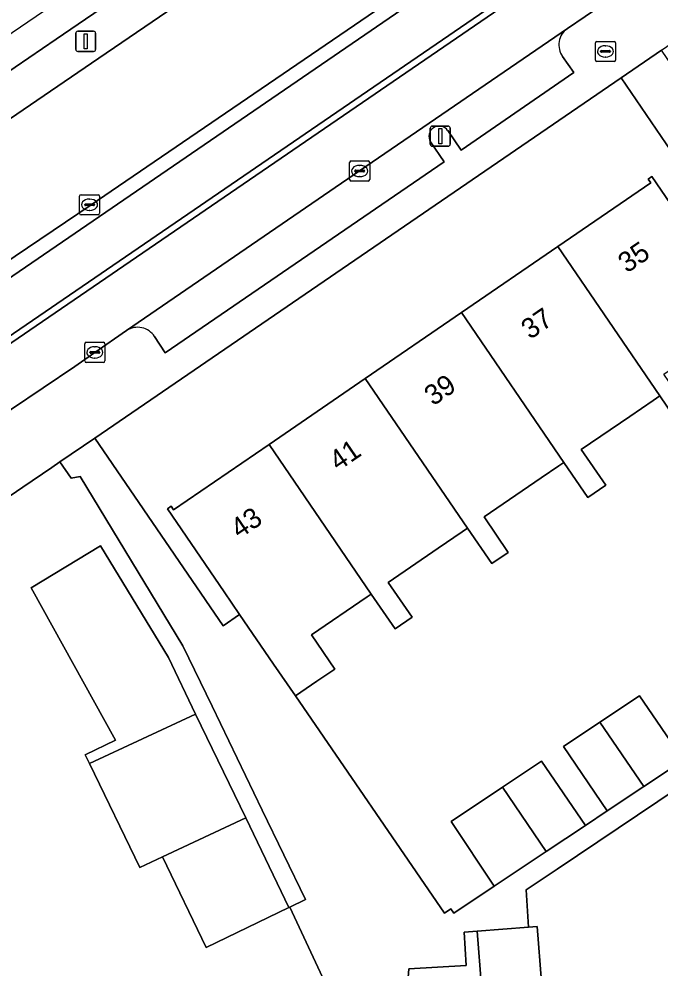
# Model space of a CAD drawing. Extents: x 158086 to 159499, y 382904 to 383981.
# Drawn here: x 158546.2 to 158578.09, y 383559.01 to 383606.24 of the extents above; entities that cross this region are included whole.
import ezdxf

# ---------------------------------------------------------------- set-up
doc = ezdxf.new("R2010")
doc.units = 0
for name, color, linetype in [('IMGEO_Berm_groen', 7, 'Continuous'), ('IMGEO_Brandkraan', 7, 'Continuous'), ('IMGEO_Erf', 7, 'Continuous'), ('IMGEO_Fietspad_gesloten', 7, 'Continuous'), ('IMGEO_Groenvoorziening', 7, 'Continuous'), ('IMGEO_Haag', 7, 'Continuous'), ('IMGEO_Kolk', 7, 'Continuous'), ('IMGEO_Lichtmast', 7, 'Continuous'), ('IMGEO_OVBaan_gesloten', 7, 'Continuous'), ('IMGEO_Pand', 7, 'Continuous'), ('IMGEO_Pand_nummerreeks', 7, 'Continuous'), ('IMGEO_Parkeervlak_open', 7, 'Continuous'), ('IMGEO_Rijbaan_lokaal_open', 7, 'Continuous'), ('IMGEO_Rijbaan_regionaal_gesloten', 7, 'Continuous'), ('IMGEO_Verkeerseiland_open', 7, 'Continuous'), ('IMGEO_Voetpad_open', 7, 'Continuous')]:
    doc.layers.add(name, color=color, linetype=linetype)

msp = doc.modelspace()

# ---------------------------------------------------------------- linework, layer by layer
at = {"layer": 'IMGEO_Berm_groen'}
msp.add_lwpolyline([(158661.52, 383682.534), (158548.056, 383605.231), (158537.837, 383598.268), (158500, 383572.487), (158425.464, 383521.701), (158412.679, 383512.917), (158399.643, 383503.685), (158401.599, 383501.25), (158412.794, 383510.243), (158418.409, 383514.401), (158426.656, 383520.079), (158500, 383570.082), (158538.968, 383596.649), (158549.805, 383604.037), (158646.334, 383669.776)], dxfattribs=at)
at = {"layer": 'IMGEO_Brandkraan'}
for p, q in [((158574.875, 383604.198), (158574.875, 383605.05)), ((158574.95, 383605.124), (158575.802, 383605.124)), ((158575.363, 383604.904), (158575.388, 383604.904)), ((158575.876, 383605.05), (158575.876, 383604.198)), ((158575.134, 383604.618), (158575.134, 383604.63)), ((158575.572, 383604.581), (158575.174, 383604.581)), ((158575.177, 383604.667), (158575.575, 383604.667)), ((158575.386, 383604.344), (158575.361, 383604.344)), ((158575.618, 383604.63), (158575.618, 383604.618)), ((158575.802, 383604.124), (158574.95, 383604.124))]:
    msp.add_line(p, q, dxfattribs=at)
for points in [[(158574.875, 383604.198), (158574.875, 383605.05)], [(158574.95, 383605.124), (158575.802, 383605.124)], [(158575.876, 383605.05), (158575.876, 383604.198)], [(158575.802, 383604.124), (158574.95, 383604.124)]]:
    msp.add_lwpolyline(points, dxfattribs=at)
for centre, radius, start, end in [((158574.952, 383605.048), 0.0765, 91.552, 178.448), ((158574.952, 383605.048), 0.0765, 91.552, 178.448), ((158575.8, 383605.048), 0.0765, 1.552, 88.448), ((158575.8, 383605.048), 0.0765, 1.552, 88.448), ((158575.174, 383604.627), 0.0403, 85.8775, 175.7526), ((158575.171, 383604.617), 0.0366, 178.938, 274.7102), ((158575.575, 383604.624), 0.043, 264.8664, 352.4533), ((158575.579, 383604.629), 0.0386, 1.7309, 96.639), ((158574.952, 383604.2), 0.0765, 181.552, 268.448), ((158574.952, 383604.2), 0.0765, 181.552, 268.448), ((158575.8, 383604.2), 0.0765, 271.552, 358.448), ((158575.8, 383604.2), 0.0765, 271.552, 358.448)]:
    msp.add_arc(centre, radius, start, end, dxfattribs=at)
for centre, major_axis, ratio, start_param, end_param in [((158575.362, 383604.624), (-0.387, 0.002), 0.722429, 4.712389, 7.853982), ((158575.387, 383604.624), (-0.39, 0.002), 0.717154, 1.570796, 4.712389)]:
    msp.add_ellipse(centre, major_axis=major_axis, ratio=ratio, start_param=start_param, end_param=end_param, dxfattribs=at)
at = {"layer": 'IMGEO_Erf'}
for points in [[(158579.136, 383598.942), (158576.159, 383603.317), (158549.967, 383585.398), (158556.351, 383576.067), (158557.177, 383576.632), (158556.403, 383577.764), (158553.583, 383581.893), (158553.765, 383582.018), (158553.889, 383581.835), (158558.644, 383585.092), (158563.43, 383588.37), (158568.214, 383591.647), (158573, 383594.925), (158577.626, 383598.094), (158577.502, 383598.276), (158577.683, 383598.4), (158582.567, 383591.251)], [(158579.125, 383585.956), (158578.072, 383587.498), (158577.748, 383587.277), (158576.58, 383586.479), (158574.174, 383584.837), (158575.386, 383583.063), (158574.494, 383582.453), (158573.305, 383584.194), (158573.059, 383584.026), (158572.184, 383583.429), (158569.339, 383581.485), (158570.543, 383579.723), (158569.719, 383579.16), (158568.513, 383580.926), (158568.251, 383580.747), (158567.051, 383579.927), (158564.567, 383578.231), (158565.754, 383576.493), (158564.911, 383575.917), (158563.728, 383577.649), (158563.528, 383577.513), (158560.75, 383575.617), (158561.909, 383573.92), (158561.021, 383573.313), (158559.951, 383572.583), (158567.367, 383561.781), (158567.688, 383561.995), (158567.831, 383561.781), (158569.84, 383563.12), (158567.693, 383566.339), (158570.248, 383568.043), (158572.194, 383569.34), (158574.377, 383566.145), (158575.464, 383566.87), (158573.281, 383570.065), (158575.095, 383571.274), (158577.07, 383572.59), (158579.253, 383569.396)], [(158561.415, 383558.361), (158559.676, 383562.084), (158560.448, 383562.457), (158558.299, 383566.908), (158555.807, 383572.069), (158554.353, 383575.08), (158549.253, 383583.496), (158548.789, 383583.404), (158548.236, 383584.214), (158547.843, 383583.945), (158546.401, 383582.959), (158522.545, 383566.673), (158524.505, 383562.65), (158524.784, 383562.729), (158527.266, 383557.496)], [(158596.657, 383500), (158593.057, 383565.667), (158592.687, 383565.654), (158592.05, 383576.787), (158572.97, 383563.972), (158571.433, 383562.939), (158571.548, 383561.088), (158571.981, 383561.122), (158572.196, 383558.372)], [(158569.201, 383558.139), (158568.986, 383560.888), (158568.35, 383560.848), (158568.454, 383559.19), (158565.586, 383559.012), (158565.569, 383558.593)]]:
    msp.add_lwpolyline(points, dxfattribs=at)
msp.add_lwpolyline([(158554.988, 383571.686), (158557.48, 383566.525), (158559.633, 383562.064), (158555.519, 383560.077), (158553.341, 383564.589), (158552.205, 383564.058), (158549.711, 383569.223), (158549.501, 383569.658), (158551.003, 383570.383), (158546.803, 383577.957), (158550.263, 383580.053), (158553.631, 383574.496)], close=True, dxfattribs=at)
at = {"layer": 'IMGEO_Fietspad_gesloten'}
for points in [[(158406.477, 383492.138), (158407.038, 383492.595), (158415.949, 383500), (158420.474, 383503.76), (158424.552, 383506.994), (158427.887, 383509.53), (158436.47, 383515.388), (158443.607, 383520.298), (158444.263, 383520.715), (158445.933, 383521.775), (158446.621, 383522.245), (158446.476, 383522.514), (158500, 383559.162), (158541.26, 383587.412), (158544.075, 383589.339), (158618.844, 383640.502), (158640.443, 383655.157), (158646.899, 383659.567), (158648.236, 383660.378)], [(158643.219, 383659.898), (158616.779, 383641.989), (158544.359, 383592.419), (158542.712, 383591.29), (158500, 383562.025), (158434.999, 383517.487), (158427.133, 383512.095)]]:
    msp.add_lwpolyline(points, dxfattribs=at)
at = {"layer": 'IMGEO_Groenvoorziening'}
for points in [[(158427.133, 383512.095), (158434.999, 383517.487), (158500, 383562.025), (158542.712, 383591.29), (158544.359, 383592.419), (158616.779, 383641.989), (158643.219, 383659.898)], [(158609.643, 383637.826), (158596.373, 383628.777), (158581.924, 383618.931), (158567.48, 383609.075), (158549.745, 383596.961), (158545.402, 383594.03), (158542.284, 383591.903), (158520.007, 383576.707), (158505.553, 383566.876), (158500, 383563.101), (158493.571, 383558.73), (158476.685, 383547.207), (158462.204, 383537.344), (158446.926, 383526.907), (158434.349, 383518.331)]]:
    msp.add_lwpolyline(points, dxfattribs=at)
at = {"layer": 'IMGEO_Haag'}
for points in [[(158427.133, 383512.095), (158434.999, 383517.487), (158500, 383562.025), (158542.712, 383591.29), (158544.359, 383592.419), (158616.779, 383641.989), (158643.219, 383659.898)], [(158609.643, 383637.826), (158596.373, 383628.777), (158581.924, 383618.931), (158567.48, 383609.075), (158549.745, 383596.961), (158545.402, 383594.03), (158542.284, 383591.903), (158520.007, 383576.707), (158505.553, 383566.876), (158500, 383563.101), (158493.571, 383558.73), (158476.685, 383547.207), (158462.204, 383537.344), (158446.926, 383526.907), (158434.349, 383518.331)]]:
    msp.add_lwpolyline(points, dxfattribs=at)
at = {"layer": 'IMGEO_Kolk'}
for p, q in [((158562.649, 383598.254), (158562.649, 383599.106)), ((158562.724, 383599.18), (158563.576, 383599.18)), ((158563.65, 383599.106), (158563.65, 383598.254)), ((158562.908, 383598.674), (158562.908, 383598.686)), ((158563.346, 383598.637), (158562.948, 383598.637)), ((158562.951, 383598.723), (158563.349, 383598.723)), ((158563.137, 383598.96), (158563.162, 383598.96)), ((158563.392, 383598.686), (158563.392, 383598.674)), ((158563.576, 383598.18), (158562.724, 383598.18)), ((158563.16, 383598.4), (158563.135, 383598.4)), ((158549.213, 383596.576), (158549.213, 383597.428)), ((158549.288, 383597.502), (158550.14, 383597.502)), ((158549.701, 383597.282), (158549.726, 383597.282)), ((158550.214, 383597.428), (158550.214, 383596.576)), ((158549.472, 383596.996), (158549.472, 383597.008)), ((158549.91, 383596.959), (158549.512, 383596.959)), ((158549.515, 383597.045), (158549.913, 383597.045)), ((158549.724, 383596.722), (158549.699, 383596.722)), ((158549.956, 383597.008), (158549.956, 383596.996)), ((158550.14, 383596.502), (158549.288, 383596.502)), ((158549.547, 383590.163), (158550.399, 383590.163)), ((158549.472, 383589.237), (158549.472, 383590.089)), ((158549.731, 383589.657), (158549.731, 383589.669)), ((158549.774, 383589.706), (158550.172, 383589.706)), ((158549.96, 383589.943), (158549.985, 383589.943)), ((158550.215, 383589.669), (158550.215, 383589.657)), ((158550.473, 383590.089), (158550.473, 383589.237)), ((158550.169, 383589.62), (158549.771, 383589.62)), ((158549.983, 383589.383), (158549.958, 383589.383)), ((158550.399, 383589.163), (158549.547, 383589.163))]:
    msp.add_line(p, q, dxfattribs=at)
for points in [[(158562.649, 383598.254), (158562.649, 383599.106)], [(158562.724, 383599.18), (158563.576, 383599.18)], [(158563.65, 383599.106), (158563.65, 383598.254)], [(158563.576, 383598.18), (158562.724, 383598.18)], [(158549.213, 383596.576), (158549.213, 383597.428)], [(158549.288, 383597.502), (158550.14, 383597.502)], [(158550.214, 383597.428), (158550.214, 383596.576)], [(158550.14, 383596.502), (158549.288, 383596.502)], [(158549.547, 383590.163), (158550.399, 383590.163)], [(158549.472, 383589.237), (158549.472, 383590.089)], [(158550.473, 383590.089), (158550.473, 383589.237)], [(158550.399, 383589.163), (158549.547, 383589.163)]]:
    msp.add_lwpolyline(points, dxfattribs=at)
for centre, radius, start, end in [((158562.726, 383599.104), 0.0765, 91.552, 178.448), ((158562.726, 383599.104), 0.0765, 91.552, 178.448), ((158563.574, 383599.104), 0.0765, 1.552, 88.448), ((158563.574, 383599.104), 0.0765, 1.552, 88.448), ((158562.948, 383598.683), 0.0403, 85.8775, 175.7526), ((158562.945, 383598.673), 0.0366, 178.938, 274.7102), ((158563.349, 383598.68), 0.043, 264.8664, 352.4533), ((158563.353, 383598.685), 0.0386, 1.7309, 96.639), ((158562.726, 383598.256), 0.0765, 181.552, 268.448), ((158562.726, 383598.256), 0.0765, 181.552, 268.448), ((158563.574, 383598.256), 0.0765, 271.552, 358.448), ((158563.574, 383598.256), 0.0765, 271.552, 358.448), ((158549.29, 383597.426), 0.0765, 91.552, 178.448), ((158549.29, 383597.426), 0.0765, 91.552, 178.448), ((158550.138, 383597.426), 0.0765, 1.552, 88.448), ((158550.138, 383597.426), 0.0765, 1.552, 88.448), ((158549.512, 383597.005), 0.0403, 85.8775, 175.7526), ((158549.509, 383596.995), 0.0366, 178.938, 274.7102), ((158549.913, 383597.002), 0.043, 264.8664, 352.4533), ((158549.917, 383597.007), 0.0386, 1.7309, 96.639), ((158549.29, 383596.578), 0.0765, 181.552, 268.448), ((158549.29, 383596.578), 0.0765, 181.552, 268.448), ((158550.138, 383596.578), 0.0765, 271.552, 358.448), ((158550.138, 383596.578), 0.0765, 271.552, 358.448), ((158549.549, 383590.087), 0.0765, 91.552, 178.448), ((158549.549, 383590.087), 0.0765, 91.552, 178.448), ((158550.397, 383590.087), 0.0765, 1.552, 88.448), ((158550.397, 383590.087), 0.0765, 1.552, 88.448), ((158549.771, 383589.666), 0.0403, 85.8775, 175.7526), ((158549.768, 383589.656), 0.0366, 178.938, 274.7102), ((158550.172, 383589.663), 0.043, 264.8664, 352.4533), ((158550.176, 383589.668), 0.0386, 1.7309, 96.639), ((158549.549, 383589.239), 0.0765, 181.552, 268.448), ((158549.549, 383589.239), 0.0765, 181.552, 268.448), ((158550.397, 383589.239), 0.0765, 271.552, 358.448), ((158550.397, 383589.239), 0.0765, 271.552, 358.448)]:
    msp.add_arc(centre, radius, start, end, dxfattribs=at)
for centre, major_axis, ratio, start_param, end_param in [((158563.136, 383598.68), (-0.387, 0.002), 0.722429, 4.712389, 7.853982), ((158563.161, 383598.68), (-0.39, 0.002), 0.717154, 1.570796, 4.712389), ((158549.7, 383597.002), (-0.387, 0.002), 0.722429, 4.712389, 7.853982), ((158549.725, 383597.002), (-0.39, 0.002), 0.717154, 1.570796, 4.712389), ((158549.959, 383589.663), (-0.387, 0.002), 0.722429, 4.712389, 7.853982), ((158549.984, 383589.663), (-0.39, 0.002), 0.717154, 1.570796, 4.712389)]:
    msp.add_ellipse(centre, major_axis=major_axis, ratio=ratio, start_param=start_param, end_param=end_param, dxfattribs=at)
at = {"layer": 'IMGEO_Lichtmast'}
for p, q in [((158549.025, 383604.725), (158549.025, 383605.525)), ((158549.025, 383605.525), (158549.025, 383604.725)), ((158549.125, 383605.625), (158549.915, 383605.625)), ((158549.915, 383605.625), (158549.125, 383605.625)), ((158550.015, 383605.525), (158550.015, 383604.725)), ((158550.015, 383604.725), (158550.015, 383605.525)), ((158549.915, 383604.625), (158549.125, 383604.625)), ((158549.125, 383604.625), (158549.915, 383604.625)), ((158566.662, 383600.011), (158566.662, 383600.811)), ((158566.662, 383600.811), (158566.662, 383600.011)), ((158566.762, 383600.911), (158567.552, 383600.911)), ((158567.552, 383600.911), (158566.762, 383600.911)), ((158567.652, 383600.811), (158567.652, 383600.011)), ((158567.652, 383600.011), (158567.652, 383600.811)), ((158567.552, 383599.911), (158566.762, 383599.911)), ((158566.762, 383599.911), (158567.552, 383599.911))]:
    msp.add_line(p, q, dxfattribs=at)
for points in [[(158549.445, 383605.5), (158549.595, 383605.5), (158549.595, 383604.75), (158549.445, 383604.75), (158549.445, 383605.5)], [(158567.082, 383600.786), (158567.232, 383600.786), (158567.232, 383600.036), (158567.082, 383600.036), (158567.082, 383600.786)]]:
    msp.add_lwpolyline(points, dxfattribs=at)
for centre, start, end in [((158549.125, 383605.525), 90, 180), ((158549.125, 383605.525), 90, 180), ((158549.915, 383605.525), 0, 90), ((158549.915, 383605.525), 360, 90), ((158549.125, 383604.725), 180, 270), ((158549.125, 383604.725), 180, 270), ((158549.915, 383604.725), 270, 0), ((158549.915, 383604.725), 270, 0), ((158566.762, 383600.811), 90, 180), ((158566.762, 383600.811), 90, 180), ((158567.552, 383600.811), 0, 90), ((158567.552, 383600.811), 360, 90), ((158566.762, 383600.011), 180, 270), ((158566.762, 383600.011), 180, 270), ((158567.552, 383600.011), 270, 0), ((158567.552, 383600.011), 270, 0)]:
    msp.add_arc(centre, 0.1, start, end, dxfattribs=at)
at = {"layer": 'IMGEO_OVBaan_gesloten'}
msp.add_lwpolyline([(158637.817, 383668.138), (158540.809, 383602.111), (158416.544, 383517.531), (158365.354, 383481.561), (158366.291, 383480.217), (158366.7, 383480.506), (158367.706, 383481.204), (158382.012, 383491.237), (158388.342, 383495.7), (158394.487, 383500), (158394.668, 383500.127), (158398.126, 383502.611), (158399.643, 383503.685), (158412.679, 383512.917), (158425.464, 383521.701), (158500, 383572.487), (158537.837, 383598.268), (158548.056, 383605.231), (158661.52, 383682.534)], dxfattribs=at)
at = {"layer": 'IMGEO_Pand'}
for points in [[(158577.683, 383598.4), (158577.502, 383598.276), (158577.626, 383598.094), (158573, 383594.925), (158578.072, 383587.498), (158579.125, 383585.956), (158579.775, 383586.4), (158578.278, 383588.588), (158582.262, 383591.308), (158582.386, 383591.126), (158582.567, 383591.251)], [(158573, 383594.925), (158568.214, 383591.647), (158573.305, 383584.194), (158574.494, 383582.453), (158575.386, 383583.063), (158574.174, 383584.837), (158576.58, 383586.479), (158577.748, 383587.277), (158578.072, 383587.498)], [(158568.214, 383591.647), (158563.43, 383588.37), (158568.513, 383580.926), (158569.719, 383579.16), (158570.543, 383579.723), (158569.339, 383581.485), (158572.184, 383583.429), (158573.059, 383584.026), (158573.305, 383584.194)], [(158563.43, 383588.37), (158558.644, 383585.092), (158563.728, 383577.649), (158564.911, 383575.917), (158565.754, 383576.493), (158564.567, 383578.231), (158567.051, 383579.927), (158568.251, 383580.747), (158568.513, 383580.926)], [(158558.644, 383585.092), (158553.889, 383581.835), (158553.765, 383582.018), (158553.583, 383581.893), (158556.403, 383577.764), (158557.177, 383576.632), (158558.867, 383574.161), (158559.951, 383572.583), (158561.021, 383573.313), (158561.909, 383573.92), (158560.75, 383575.617), (158563.528, 383577.513), (158563.728, 383577.649)], [(158549.711, 383569.223), (158554.988, 383571.686), (158553.631, 383574.496), (158550.263, 383580.053), (158546.803, 383577.957), (158551.003, 383570.383), (158549.501, 383569.658)], [(158577.07, 383572.59), (158575.095, 383571.274), (158577.278, 383568.079), (158579.253, 383569.396)], [(158554.988, 383571.686), (158549.711, 383569.223), (158552.205, 383564.058), (158553.341, 383564.589), (158557.48, 383566.525)], [(158575.095, 383571.274), (158573.281, 383570.065), (158575.464, 383566.87), (158577.278, 383568.079)], [(158572.194, 383569.34), (158570.248, 383568.043), (158572.431, 383564.848), (158574.377, 383566.145)], [(158570.248, 383568.043), (158567.693, 383566.339), (158569.84, 383563.12), (158572.431, 383564.848)], [(158557.48, 383566.525), (158553.341, 383564.589), (158555.519, 383560.077), (158559.633, 383562.064)], [(158571.548, 383561.088), (158568.986, 383560.888), (158569.201, 383558.139), (158572.196, 383558.372), (158571.981, 383561.122)]]:
    msp.add_lwpolyline(points, close=True, dxfattribs=at)
at = {"layer": 'IMGEO_Parkeervlak_open'}
for points in [[(158573.479, 383605.764), (158563.146, 383598.681), (158551.551, 383590.748)], [(158567.526, 383600.691), (158568.201, 383599.715), (158573.8, 383603.57), (158573.246, 383604.372)], [(158552.944, 383590.449), (158553.476, 383589.647), (158567.352, 383599.137), (158566.676, 383600.126)]]:
    msp.add_lwpolyline(points, dxfattribs=at)
for centre, radius, start, end in [((158574.044, 383604.954), 0.988, 124.9067, 216.0885), ((158567.104, 383600.404), 0.51, 34.1912, 213.0332), ((158552.099, 383589.906), 1.005, 32.7348, 123.0364)]:
    msp.add_arc(centre, radius, start, end, dxfattribs=at)
at = {"layer": 'IMGEO_Rijbaan_lokaal_open'}
for points in [[(158646.837, 383659.134), (158640.621, 383654.875), (158619.029, 383640.224), (158544.259, 383589.076), (158541.457, 383587.159), (158500, 383558.782), (158446.621, 383522.245), (158445.933, 383521.775)], [(158509.297, 383561.87), (158518.272, 383568.017), (158520.325, 383569.401), (158527.122, 383574.06), (158535.161, 383579.515), (158543.008, 383584.914), (158543.436, 383585.211), (158545.232, 383586.434), (158545.824, 383586.835), (158548.973, 383588.965), (158549.969, 383589.664), (158551.551, 383590.748), (158563.146, 383598.681), (158573.479, 383605.764), (158577, 383608.163)]]:
    msp.add_lwpolyline(points, dxfattribs=at)
at = {"layer": 'IMGEO_Rijbaan_regionaal_gesloten'}
for points in [[(158646.334, 383669.776), (158549.805, 383604.037), (158538.968, 383596.649), (158500, 383570.082), (158426.656, 383520.079)], [(158434.349, 383518.331), (158446.926, 383526.907), (158462.204, 383537.344), (158476.685, 383547.207), (158493.571, 383558.73), (158500, 383563.101), (158505.553, 383566.876), (158520.007, 383576.707), (158542.284, 383591.903), (158545.402, 383594.03), (158549.745, 383596.961), (158567.48, 383609.075), (158581.924, 383618.931), (158596.373, 383628.777), (158609.643, 383637.826)]]:
    msp.add_lwpolyline(points, dxfattribs=at)
at = {"layer": 'IMGEO_Verkeerseiland_open'}
msp.add_lwpolyline([(158649.379, 383658.827), (158648.905, 383659.524), (158648.236, 383660.378), (158646.899, 383659.567), (158640.443, 383655.157), (158618.844, 383640.502), (158544.075, 383589.339), (158541.26, 383587.412), (158500, 383559.162), (158446.476, 383522.514), (158446.621, 383522.245), (158500, 383558.782), (158541.457, 383587.159), (158544.259, 383589.076), (158619.029, 383640.224), (158640.621, 383654.875), (158646.837, 383659.134)], dxfattribs=at)
at = {"layer": 'IMGEO_Voetpad_open'}
for points in [[(158583.69, 383608.497), (158588.804, 383611.969), (158588.809, 383611.645), (158588.859, 383611.241), (158592.055, 383614.205), (158595.723, 383620.99), (158590.586, 383617.443), (158590.366, 383617.3), (158590.981, 383616.4), (158580.357, 383609.147), (158579.742, 383610.047), (158577, 383608.163), (158573.479, 383605.764)], [(158527.122, 383574.06), (158520.325, 383569.401), (158518.272, 383568.017), (158522.545, 383566.673), (158546.401, 383582.959), (158547.843, 383583.945), (158548.236, 383584.214), (158549.967, 383585.398), (158576.159, 383603.317), (158578.168, 383604.68), (158583.69, 383608.497)], [(158573.246, 383604.372), (158573.8, 383603.57), (158568.201, 383599.715), (158567.526, 383600.691)], [(158595.015, 383577.001), (158596.929, 383577.033), (158596.83, 383579.058), (158594.841, 383578.942), (158594.665, 383580.73), (158592.169, 383584.383), (158593.612, 383587.565), (158591.554, 383591.767), (158590.347, 383587.05), (158582.919, 383597.717), (158578.168, 383604.68), (158576.159, 383603.317), (158579.136, 383598.942), (158591.872, 383579.897), (158591.909, 383579.25), (158592.05, 383576.787), (158592.687, 383565.654), (158593.057, 383565.667), (158596.657, 383500), (158597.492, 383485.05), (158598.535, 383465.518), (158596.553, 383455.707), (158599.516, 383455.549)], [(158566.676, 383600.126), (158567.352, 383599.137), (158553.476, 383589.647), (158552.944, 383590.449)], [(158551.551, 383590.748), (158549.969, 383589.664), (158548.973, 383588.965), (158545.824, 383586.835), (158545.232, 383586.434), (158543.436, 383585.211), (158543.008, 383584.914)], [(158579.253, 383569.396), (158577.278, 383568.079), (158575.464, 383566.87), (158574.377, 383566.145), (158572.431, 383564.848), (158569.84, 383563.12), (158567.831, 383561.781), (158567.688, 383561.995), (158567.367, 383561.781), (158559.951, 383572.583), (158558.867, 383574.161), (158557.177, 383576.632), (158556.351, 383576.067), (158549.967, 383585.398), (158548.236, 383584.214), (158548.789, 383583.404), (158549.253, 383583.496), (158554.353, 383575.08), (158555.807, 383572.069), (158558.299, 383566.908), (158560.448, 383562.457), (158559.676, 383562.084), (158561.415, 383558.361)], [(158565.569, 383558.593), (158565.586, 383559.012), (158568.454, 383559.19), (158568.35, 383560.848), (158568.986, 383560.888), (158571.548, 383561.088), (158571.433, 383562.939), (158572.97, 383563.972), (158592.05, 383576.787)]]:
    msp.add_lwpolyline(points, dxfattribs=at)
for centre, radius, start, end in [((158574.044, 383604.954), 0.988, 124.9067, 216.0885), ((158567.104, 383600.404), 0.51, 34.1912, 213.0332), ((158552.099, 383589.906), 1.005, 32.7348, 123.0364)]:
    msp.add_arc(centre, radius, start, end, dxfattribs=at)

# ---------------------------------------------------------------- texts
at = {"layer": 'IMGEO_Pand_nummerreeks'}
for s, p in [('35', (158576.445, 383593.577)), ('37', (158571.625, 383590.275)), ('39', (158566.805, 383586.974)), ('41', (158562.078, 383583.737)), ('43', (158557.165, 383580.371))]:
    msp.add_text(s, height=1, rotation=34.4061, dxfattribs=at).set_placement(p)

doc.saveas('drawing.dxf')
